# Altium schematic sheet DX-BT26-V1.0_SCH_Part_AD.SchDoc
size A4
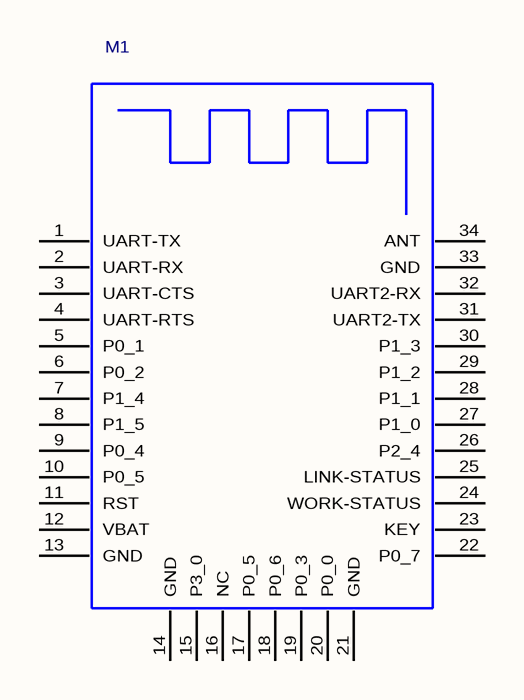
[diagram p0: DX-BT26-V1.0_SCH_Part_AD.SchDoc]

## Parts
M1  DX-BT26  [DX-BT26]  (value not drawn)

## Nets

Not connected (* = marked no-connect by the designer): M1 1(UART-TX) 2(UART-RX) 3(UART-CTS) 4(UART-RTS) 5(P0_1) 6(P0_2) 7(P1_4) 8(P1_5) 9(P0_4) 10(P0_5) 11(RST) 12(VBAT) 13(GND) 14(GND) 15(P3_0) 16(NC) 17(P0_5) 18(P0_6) 19(P0_3) 20(P0_0) 21(GND) 22(P0_7) 23(KEY) 24(WORK-STATUS) 25(LINK-STATUS) 26(P2_4) 27(P1_0) 28(P1_1) 29(P1_2) 30(P1_3) 31(UART2-TX) 32(UART2-RX) 33(GND) 34(ANT)

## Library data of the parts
M1 = DX-BT26: PCB DECAL: DX-BT24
